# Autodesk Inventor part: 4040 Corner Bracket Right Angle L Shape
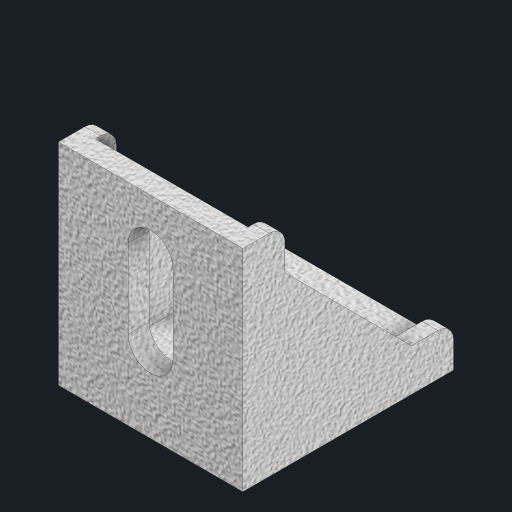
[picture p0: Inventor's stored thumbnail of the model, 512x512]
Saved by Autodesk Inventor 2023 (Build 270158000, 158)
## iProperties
Created: 2024-07
Part Number: 4040 Corner Bracket Right Angle L Shape
Material: Aluminum 6061
Document SubType Name: Modeling
Designer: chris
Density: 2.7 g/cm^3
Appearance: Aluminum Cast
Author: chris
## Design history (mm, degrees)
sketch "Sketch1"
  geometry: L1 (0, 0)-(-35, 0); L2 (-35, 0)-(-35, -40); L3 (-35, -40)-(0, -40); L4 (0, -40)-(0, 0)
  constraints: 8 end point, 2 parallel, 1 horizontal, 1 perpendicular
  dimensions: "d0" = 35 distance of L1.start L1.end; "d1" = 40 distance of L3.end L1.start
extrude "Extrusion1" new body sketch "Sketch1" distance "d2" = 4; taper "d3" = 0 deg
sketch "Sketch2"
  geometry: L1 (0, 0)-(35, 0) reference; L2 (35, 0)-(35, 4) reference; L3 (0, 4)-(35, 4) reference; L4 (0, 0)-(0, 4) reference; L5 (35, 0)-(0, 0) reference; L6 (0, 0)-(35, 0); L7 (35, 0)-(35, 40); L8 (35, 40)-(0, 40); L9 (0, 40)-(0, 0); 3 further points
  constraints: 8 end point, 2 parallel, 1 horizontal, 1 perpendicular
  dimensions: "d4" = 40 distance between parallel lines of L1 L8; "d5" = 35 distance between parallel lines of L7 L9
extrude "Extrusion2" join sketch "Sketch2" distance "d6" = 4; taper "d7" = 0 deg
sketch "Sketch3"
  geometry: L1 (0, 4)-(35, 4) reference; L2 (35, 4)-(35, 40) reference; L3 (35, 40)-(0, 40) reference; L4 (0, 40)-(0, 4) reference; L5 (35, 0)-(0, 0) reference; L6 (-16.2, 20)-(66.463, 20); L7 (0, 4)-(35, 4) reference; L8 (17.5, -18.042)-(17.5, 51.486); L9 (13.25, 15)-(13.25, 30); L10 (21.75, 15)-(21.75, 30); A1 r 4.25 centre (17.5, 15) between (13.25, 15) and (21.75, 15); A2 r 4.25 centre (17.5, 30) between (21.75, 30) and (13.25, 30)
  constraints: 8 end point, 4 point on circle, 2 centre point, 2 parallel, 2 tangent, 2 vertical
  dimensions: "d8" = 8.5 diameter of A1; "d9" = 8.5 diameter of A2; "d10" = 0 horizontal distance of A1.centre A2.centre; "d11" = 20 distance between parallel lines of L5 L6 (= 0.5 x d12); "d12" = 40 distance between parallel lines of L3 L5 (derived); "d15" = 35 distance between parallel lines of L2 L4 (derived); "d16" = 17.5 distance between parallel lines of L4 L8 (= 0.5 x d15); "d17" = 0 distance from line of L8 A1.centre; "d20" = 15 distance from line of L5 A1.centre; "d21" = 10 distance from line of L3 A2.centre
extrude "Extrusion3" cut sketch "Sketch3" distance "d22" = 4; taper "d23" = 0 deg
sketch "Sketch4"
  geometry: L1 (0, 0)-(-35, 0) reference; L2 (-35, 0)-(-35, 40) reference; L3 (-35, 40)-(0, 40) reference; L4 (0, 0)-(0, 40) reference; L5 (-13.25, 30)-(-13.25, 15); L6 (-21.75, 30)-(-21.75, 15); A1 r 4.25 centre (-17.5, 15) between (-21.75, 15) and (-13.25, 15); A2 r 4.25 centre (-17.5, 30) between (-13.25, 30) and (-21.75, 30); 2 further points
  constraints: 4 end point, 4 point on circle, 3 tangent, 2 centre point, 1 midpoint
  dimensions: "d24" = 8.5 diameter of A1; "d25" = 8.5 diameter of A2 (= d24); "d27" = 10 distance from line of A2.centre L3; "d28" = 15 distance of point (-17.5, 0) A1.centre; "d29" = 0 horizontal distance of A1.centre A2.centre; "d30" = 35 distance between parallel lines of L4 L2 (derived); "d31" = 17.5 distance from line of L4 A2.centre (= 0.5 x d30)
extrude "Extrusion4" cut sketch "Sketch4" distance "d32" = 4; taper "d33" = 0 deg
sketch "Sketch5"
  geometry: L1 (40, 0)-(40, 4) reference; L2 (40, 0)-(0, 0); L3 (0, 0)-(0, 40); L4 (4, 40)-(4, 4) reference; L5 (8, 40)-(8, 32); L6 (40, 8)-(32, 8); L7 (8, 32)-(32, 8); L8 (40, 0)-(40, 8); L9 (0, 40)-(4, 40) reference; L10 (0, 40)-(8, 40); 3 further points
  constraints: 14 end point, 2 vertical, 1 collinear, 1 horizontal, 1 perpendicular
  dimensions: "d36" = 8 distance of L5.start L5.end; "d37" = 8 distance of L6.start L6.end; "d39" = 8 distance of L1.start L6.start; "d40" = 8 distance of L3.end L5.start
extrude "Extrusion5" join sketch "Sketch5" distance "d41" = 3; taper "d42" = 0 deg
fillet "Fillet1" dims "d43" = 3
workplane "Work Plane1"
workplane "Work Plane2"
mirror "Mirror1"
body "Solid1"
node "Projected Loop1"
node "Projected Loop2"
node "Projected Loop3"
